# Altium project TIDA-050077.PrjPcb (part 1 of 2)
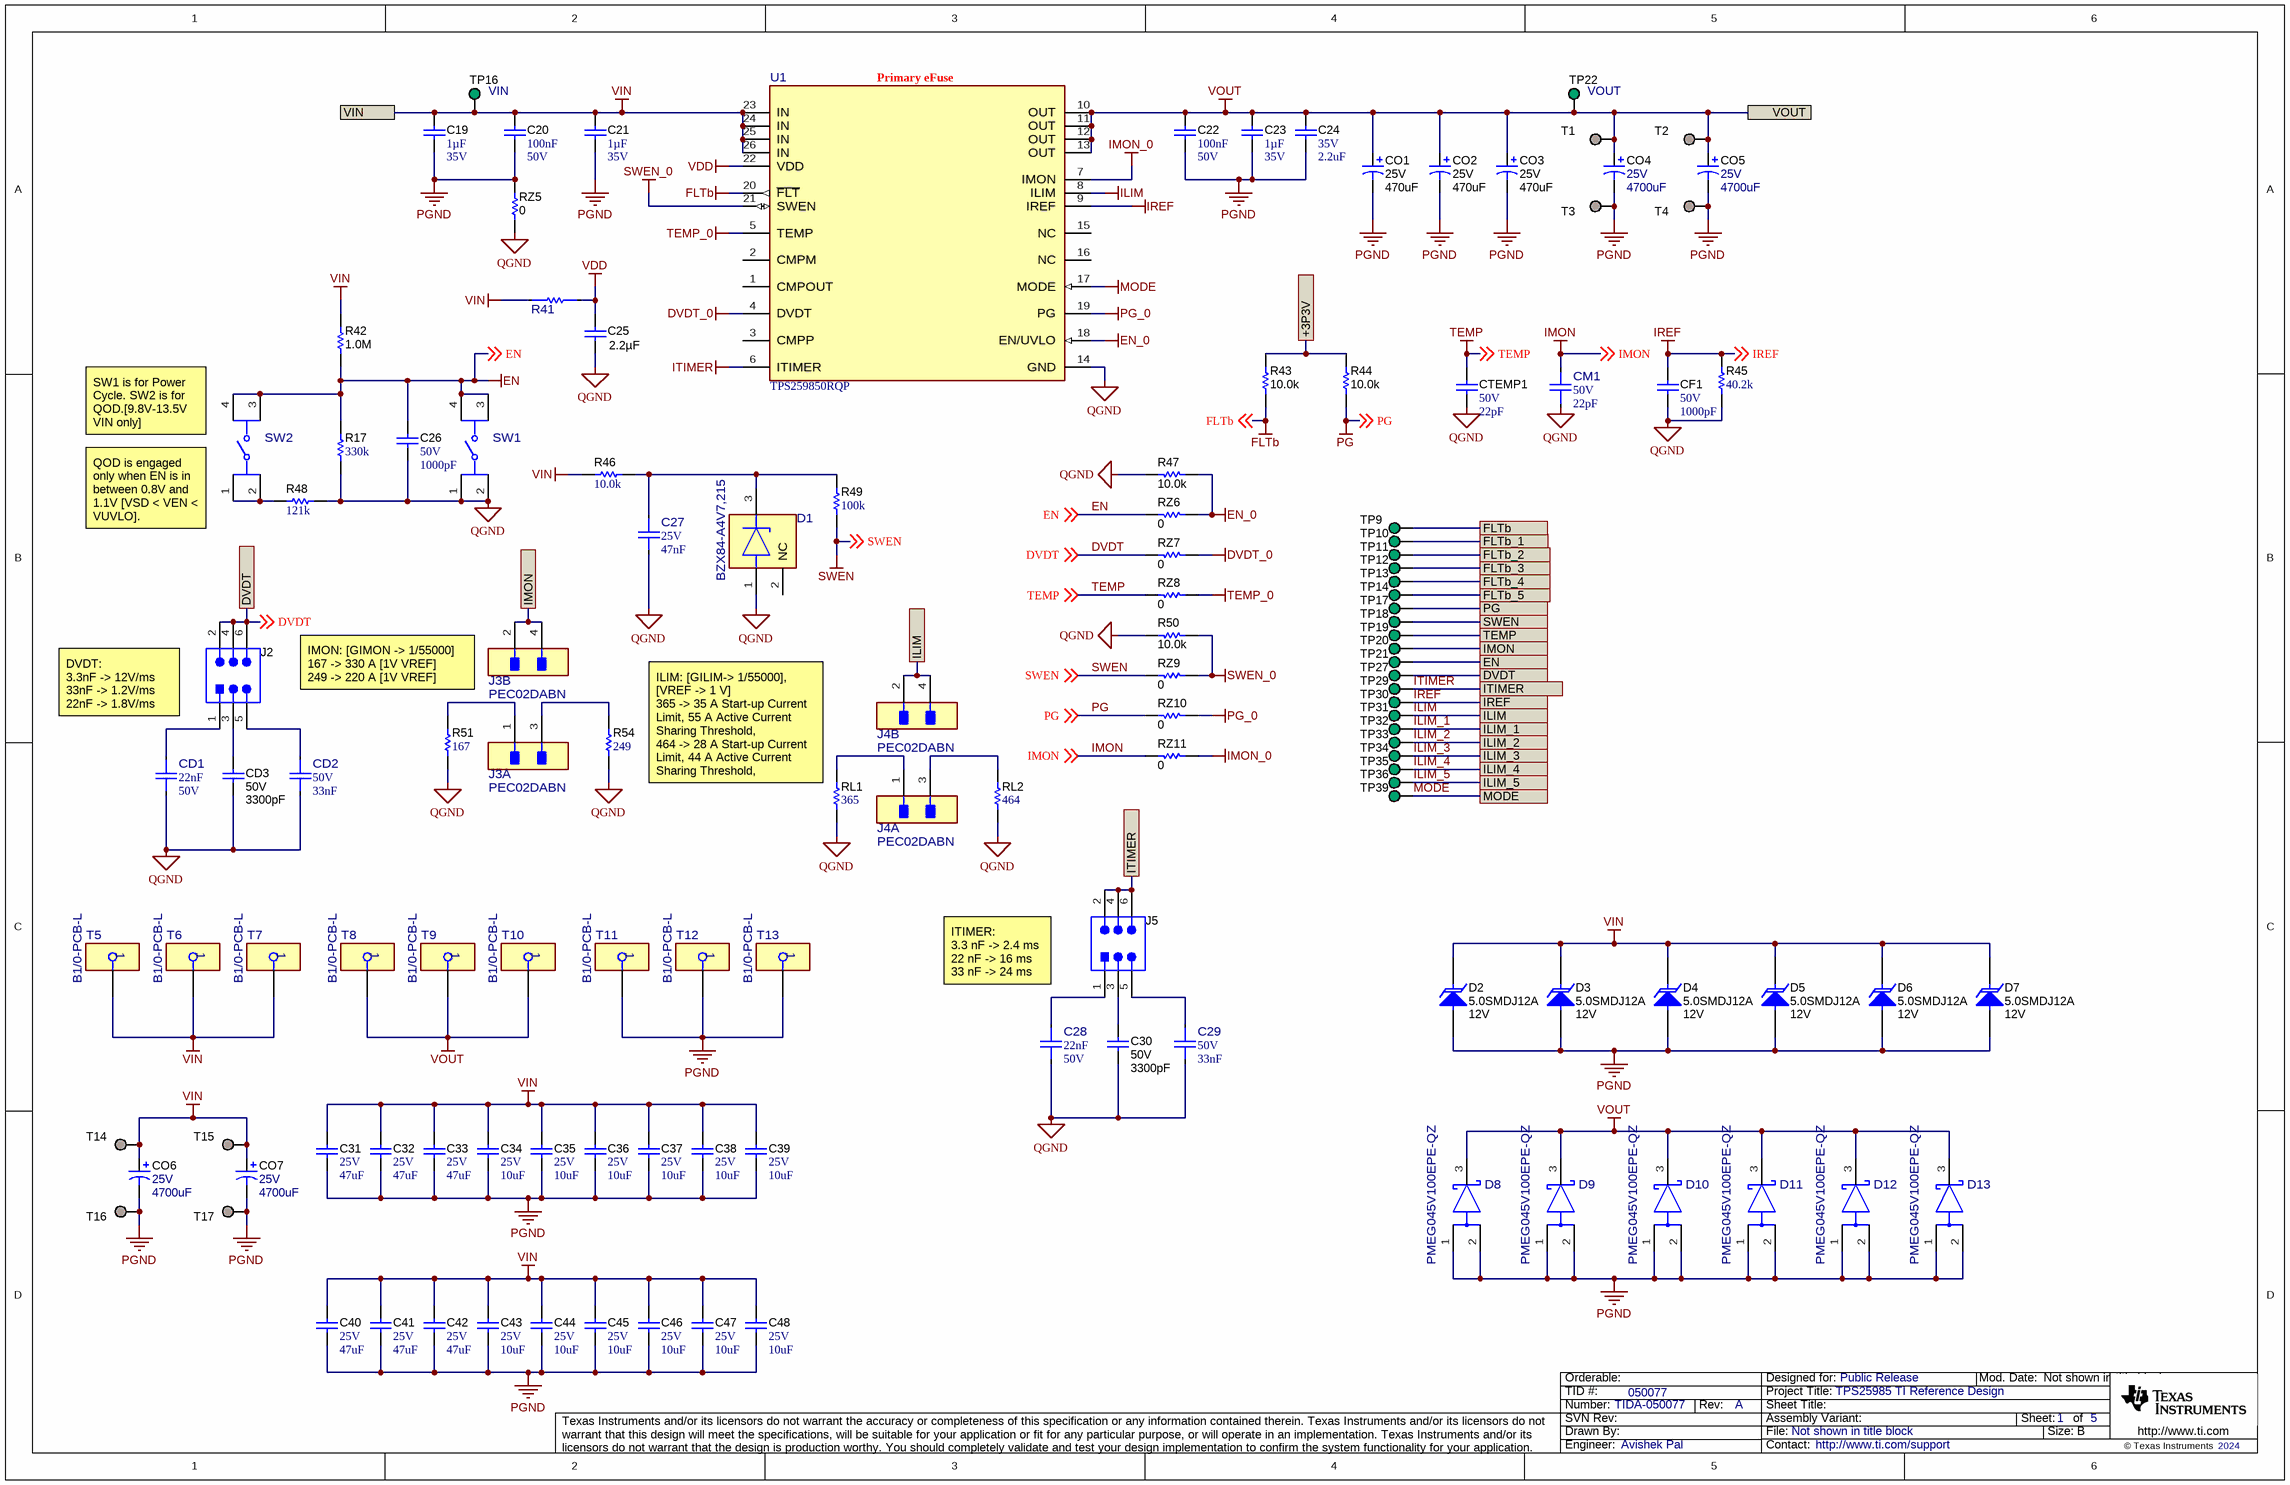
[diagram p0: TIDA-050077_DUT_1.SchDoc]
CopyrightYear: 2024; PCB_Rev: A; PRJ_Customer: Public Release; PRJ_Engineer: Avishek Pal; PRJ_Number: TIDA-050077; PRJ_Title: TPS25985 TI Reference Design; SCH_Rev: A; TechSupport: http://www.ti.com/support; TID: 050077
5 sheets, 376 parts. Net scope: flat (ports and power ports of the same name join across sheets).
Board file: TIDA-050077_PCB-112723-1m.PcbDoc
Sheets:
  TIDA-050077_DUT_1.SchDoc
  TIDA-050077_DUT_2_3_4.SchDoc
  TIDA-050077_DUT_5_6.SchDoc
  TIDA-050077_HKeeping.SchDoc
  TIDA-050077_Hardware.SchDoc

## Sheet TIDA-050077_DUT_1.SchDoc
size 431 x 279 mm; Date: Not shown in title block; ApprovedBy: Not shown in title block; CheckedBy: Not shown in title block; Author: Not shown in title block; CompanyName: Not shown in title block; Engineer: Not shown in title block; Organization: Not shown in title block; Address1: Not shown in title block; Address2: Not shown in title block; Address3: Not shown in title block; Address4: Not shown in title block; DocumentNumber: 1; Revision: Use project parameter SCH_Rev; SheetNumber: 1; SheetTotal: 5; PageSetup: Record=PageOptions¦CenterHorizontal=True¦CenterVertical=True¦PrintScale=1.00¦XCorrection=1.00¦YCorrection=1.00¦PrintKind=0¦BorderSize=5000000¦LeftOffset=0¦BottomOffset=0¦Orientation=2¦PaperLength=1000¦PaperWidth=1000¦Scale=100¦PaperSource=15¦PrintQuality=600¦MediaType=1¦DitherType=10¦PaperKind=Letter¦PrintScaleMode=1

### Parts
C19  Cap_F: 1µF  VDC_V: 35V  [0603]  (hidden comment: C1608X7R1V105K080AC)
C20  Cap_F: 100nF  VDC_V: 50V  [0603]  (hidden comment: C0603C104K5RACAUTO)
C21  Cap_F: 1µF  VDC_V: 35V  [0603]  (hidden comment: C1608X7R1V105K080AC)
C22  Cap_F: 100nF  VDC_V: 50V  [0603]  (hidden comment: C0603C104K5RACAUTO)
C23  Cap_F: 1µF  VDC_V: 35V  [0603]  (hidden comment: C1608X7R1V105K080AC)
C24  VDC_V: 35V  ValueDisplayed: 2.2uF  [0603]  (hidden comment: GRM188R6YA225KA12D)
C25  ValueDisplayed: 2.2µF  [0603L]  (hidden comment: GRM188C71E225KE11D)
C26  VDC_V: 50V  ValueDisplayed: 1000pF  [0603]  (hidden comment: GRM1885C1H102JA01D)
C27  VDC_V: 25V  Cap_F: 47nF  [FP-C0603C473J3RAC7867_0603-MFG]  (hidden comment: C0603C473J3RAC7867)
C28  Cap_F: 22nF  VDC_V: 50V  [FP-GCJ188R71H223KA01D_0603-MFG]  (hidden comment: GCJ188R71H223KA01D)
C29  VDC_V: 50V  Cap_F: 33nF  [FP-GCJ188R71H333KA12D_0603-MFG]  (hidden comment: GCJ188R71H333KA12D)
C30  VDC_V: 50V  ValueDisplayed: 3300pF  [0603]  (hidden comment: GRM1885C1H332JA01D)
C31  VDC_V: 25V  ValueDisplayed: 47uF  [CKG57N]  (hidden comment: CKG57NX7S1E476M500JH)
C32  VDC_V: 25V  ValueDisplayed: 47uF  [CKG57N]  (hidden comment: CKG57NX7S1E476M500JH)
C33  VDC_V: 25V  ValueDisplayed: 47uF  [CKG57N]  (hidden comment: CKG57NX7S1E476M500JH)
C34  VDC_V: 25V  ValueDisplayed: 10uF  [0805_HV]  (hidden comment: C2012X5R1E106K125AB)
C35  VDC_V: 25V  ValueDisplayed: 10uF  [0805_HV]  (hidden comment: C2012X5R1E106K125AB)
C36  VDC_V: 25V  ValueDisplayed: 10uF  [0805_HV]  (hidden comment: C2012X5R1E106K125AB)
C37  VDC_V: 25V  ValueDisplayed: 10uF  [0805_HV]  (hidden comment: C2012X5R1E106K125AB)
C38  VDC_V: 25V  ValueDisplayed: 10uF  [0805_HV]  (hidden comment: C2012X5R1E106K125AB)
C39  VDC_V: 25V  ValueDisplayed: 10uF  [0805_HV]  (hidden comment: C2012X5R1E106K125AB)
C40  VDC_V: 25V  ValueDisplayed: 47uF  [CKG57N]  (hidden comment: CKG57NX7S1E476M500JH)
C41  VDC_V: 25V  ValueDisplayed: 47uF  [CKG57N]  (hidden comment: CKG57NX7S1E476M500JH)
C42  VDC_V: 25V  ValueDisplayed: 47uF  [CKG57N]  (hidden comment: CKG57NX7S1E476M500JH)
C43  VDC_V: 25V  ValueDisplayed: 10uF  [0805_HV]  (hidden comment: C2012X5R1E106K125AB)
C44  VDC_V: 25V  ValueDisplayed: 10uF  [0805_HV]  (hidden comment: C2012X5R1E106K125AB)
C45  VDC_V: 25V  ValueDisplayed: 10uF  [0805_HV]  (hidden comment: C2012X5R1E106K125AB)
C46  VDC_V: 25V  ValueDisplayed: 10uF  [0805_HV]  (hidden comment: C2012X5R1E106K125AB)
C47  VDC_V: 25V  ValueDisplayed: 10uF  [0805_HV]  (hidden comment: C2012X5R1E106K125AB)
C48  VDC_V: 25V  ValueDisplayed: 10uF  [0805_HV]  (hidden comment: C2012X5R1E106K125AB)
CD1  Cap_F: 22nF  VDC_V: 50V  [FP-GCJ188R71H223KA01D_0603-MFG]  (hidden comment: GCJ188R71H223KA01D)
CD2  VDC_V: 50V  Cap_F: 33nF  [FP-GCJ188R71H333KA12D_0603-MFG]  (hidden comment: GCJ188R71H333KA12D)
CD3  VDC_V: 50V  ValueDisplayed: 3300pF  [0603]  (hidden comment: GRM1885C1H332JA01D)
CF1  VDC_V: 50V  ValueDisplayed: 1000pF  [0402]  (hidden comment: CGA2B2C0G1H102J050BA)
CM1  VDC_V: 50V  ValueDisplayed: 22pF  [FP-GCG1885G1H220JA01D_0603-IPC_C]  (hidden comment: GCG1885G1H220JA01D)
CO1  VDC_V: 25V  ValueDisplayed: 470uF  [CAPSMT_62_JA0]  (hidden comment: EMVE250ADA471MJA0G)
CO2  VDC_V: 25V  ValueDisplayed: 470uF  [CAPSMT_62_JA0]  (hidden comment: EMVE250ADA471MJA0G)
CO3  VDC_V: 25V  ValueDisplayed: 470uF  [CAPSMT_62_JA0]  (hidden comment: EMVE250ADA471MJA0G)
CO4  VDC_V: 25V  ValueDisplayed: 4700uF  [KMQ_1600x2500]  (hidden comment: EKMQ250EIV472ML25S)
CO5  VDC_V: 25V  ValueDisplayed: 4700uF  [KMQ_1600x2500]  (hidden comment: EKMQ250EIV472ML25S)
CO6  VDC_V: 25V  ValueDisplayed: 4700uF  [KMQ_1600x2500]  (hidden comment: EKMQ250EIV472ML25S)
CO7  VDC_V: 25V  ValueDisplayed: 4700uF  [KMQ_1600x2500]  (hidden comment: EKMQ250EIV472ML25S)
CTEMP1  VDC_V: 50V  ValueDisplayed: 22pF  [0603]  (hidden comment: 06035A220JAT2A)
D1  BZX84-A4V7,215  [FP-BZX84-A4V7,215_SOT23-3-MFG]
D2  5.0SMDJ12A  value 12V  [SMC]
D3  5.0SMDJ12A  value 12V  [SMC]
D4  5.0SMDJ12A  value 12V  [SMC]
D5  5.0SMDJ12A  value 12V  [SMC]
D6  5.0SMDJ12A  value 12V  [SMC]
D7  5.0SMDJ12A  value 12V  [SMC]
D8  PMEG045V100EPE-QZ  [FP-PMEG045V100EPE-QZ_CFP15B-MFG]
D9  PMEG045V100EPE-QZ  [FP-PMEG045V100EPE-QZ_CFP15B-MFG]
D10  PMEG045V100EPE-QZ  [FP-PMEG045V100EPE-QZ_CFP15B-MFG]
D11  PMEG045V100EPE-QZ  [FP-PMEG045V100EPE-QZ_CFP15B-MFG]
D12  PMEG045V100EPE-QZ  [FP-PMEG045V100EPE-QZ_CFP15B-MFG]
D13  PMEG045V100EPE-QZ  [FP-PMEG045V100EPE-QZ_CFP15B-MFG]
J2  PEC03DAAN  [SULLINS_PEC03DAAN]  (value not drawn)
J3  PEC02DABN  [FP-PEC02DABN_HDR4-MFG]  (parts A,B of 2)
J4  PEC02DABN  [FP-PEC02DABN_HDR4-MFG]  (parts A,B of 2)
J5  PEC03DAAN  [SULLINS_PEC03DAAN]  (value not drawn)
R17  ValueDisplayed: 330k  [0402]  (hidden comment: CRCW0402330KFKED)
R41  RC0603JR-0710RL  [FP-RC0603JR-0710RL_0603-MFG]  (value not drawn)
R42  ValueDisplayed: 1.0M  [0402L]  (hidden comment: CRCW04021M00JNED)
R43  ValueDisplayed: 10.0k  [0402]  (hidden comment: RC0402FR-0710KL)
R44  ValueDisplayed: 10.0k  [0402]  (hidden comment: RC0402FR-0710KL)
R45  ValueDisplayed: 40.2k  [0603]  (hidden comment: RT0603BRD0740K2L)
R46  ValueDisplayed: 10.0k  [0603]  (hidden comment: CRCW060310K0FKEA)
R47  ValueDisplayed: 10.0k  [0402]  (hidden comment: RC0402FR-0710KL)
R48  ValueDisplayed: 121k  [0603]  (hidden comment: RC0603FR-07121KL)
R49  ValueDisplayed: 100k  [0402]  (hidden comment: CRCW0402100KFKED)
R50  ValueDisplayed: 10.0k  [0402]  (hidden comment: RC0402FR-0710KL)
R51  ValueDisplayed: 167  [0603]  (hidden comment: RT0603BRD07167RL)
R54  ValueDisplayed: 249  [0603]  (hidden comment: RT0603BRD07249RL)
RL1  ValueDisplayed: 365  [0603]  (hidden comment: RT0603BRD07365RL)
RL2  ValueDisplayed: 464  [0603]  (hidden comment: RT0603BRD07464RL)
RZ5  ValueDisplayed: 0  [0402]  (hidden comment: CRCW04020000Z0ED)
RZ6  ValueDisplayed: 0  [0402]  (hidden comment: CRCW04020000Z0ED)
RZ7  ValueDisplayed: 0  [0402]  (hidden comment: CRCW04020000Z0ED)
RZ8  ValueDisplayed: 0  [0402]  (hidden comment: CRCW04020000Z0ED)
RZ9  ValueDisplayed: 0  [0402]  (hidden comment: CRCW04020000Z0ED)
RZ10  ValueDisplayed: 0  [0402]  (hidden comment: CRCW04020000Z0ED)
RZ11  ValueDisplayed: 0  [0402]  (hidden comment: CRCW04020000Z0ED)
SW1  PTS830GM140SMTRLFS  [FP-PTS830GM140SMTRLFS_SMT_3MM05_2MM6-MFG]  (value not drawn)
SW2  PTS830GM140SMTRLFS  [FP-PTS830GM140SMTRLFS_SMT_3MM05_2MM6-MFG]  (value not drawn)
T1  Turret  [CONN_ 0300-2-15-01-47-01-10-0]  (value not drawn)
T2  Turret  [CONN_ 0300-2-15-01-47-01-10-0]  (value not drawn)
T3  Turret  [CONN_ 0300-2-15-01-47-01-10-0]  (value not drawn)
T4  Turret  [CONN_ 0300-2-15-01-47-01-10-0]  (value not drawn)
T5  B1/0-PCB-L  [FP-B1-0-PCB-L_WIRE_LUG_150A_1-0AWG-MFG]
T6  B1/0-PCB-L  [FP-B1-0-PCB-L_WIRE_LUG_150A_1-0AWG-MFG]
T7  B1/0-PCB-L  [FP-B1-0-PCB-L_WIRE_LUG_150A_1-0AWG-MFG]
T8  B1/0-PCB-L  [FP-B1-0-PCB-L_WIRE_LUG_150A_1-0AWG-MFG]
T9  B1/0-PCB-L  [FP-B1-0-PCB-L_WIRE_LUG_150A_1-0AWG-MFG]
T10  B1/0-PCB-L  [FP-B1-0-PCB-L_WIRE_LUG_150A_1-0AWG-MFG]
T11  B1/0-PCB-L  [FP-B1-0-PCB-L_WIRE_LUG_150A_1-0AWG-MFG]
T12  B1/0-PCB-L  [FP-B1-0-PCB-L_WIRE_LUG_150A_1-0AWG-MFG]
T13  B1/0-PCB-L  [FP-B1-0-PCB-L_WIRE_LUG_150A_1-0AWG-MFG]
T14  Turret  [CONN_ 0300-2-15-01-47-01-10-0]  (value not drawn)
T15  Turret  [CONN_ 0300-2-15-01-47-01-10-0]  (value not drawn)
T16  Turret  [CONN_ 0300-2-15-01-47-01-10-0]  (value not drawn)
T17  Turret  [CONN_ 0300-2-15-01-47-01-10-0]  (value not drawn)
TP9  (no value)  [Keystone5126]
TP10  (no value)  [Keystone5126]
TP11  (no value)  [Keystone5126]
TP12  (no value)  [Keystone5126]
TP13  (no value)  [Keystone5126]
TP14  (no value)  [Keystone5126]
TP16  VIN  [Keystone5126]
TP17  (no value)  [Keystone5126]
TP18  (no value)  [Keystone5126]
TP19  (no value)  [Keystone5126]
TP20  (no value)  [Keystone5126]
TP21  (no value)  [Keystone5126]
TP22  VOUT  [Keystone5126]
TP27  (no value)  [Keystone5126]
TP29  (no value)  [Keystone5126]
TP30  (no value)  [Keystone5126]
TP31  (no value)  [Keystone5126]
TP32  (no value)  [Keystone5126]
TP33  (no value)  [Keystone5126]
TP34  (no value)  [Keystone5126]
TP35  (no value)  [Keystone5126]
TP36  (no value)  [Keystone5126]
TP39  (no value)  [Keystone5126]
U1  TPS259850RQP  [RQP0026A-MFG]

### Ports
+3P3V, DVDT, EN, FLTb, FLTb_1, FLTb_2, FLTb_3, FLTb_4, FLTb_5, ILIM, ILIM_1, ILIM_2, ILIM_3, ILIM_4, ILIM_5, IMON, IREF, ITIMER, MODE, PG, SWEN, TEMP, VIN, VOUT

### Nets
+3P3V: R43.1 R44.1 ; port +3P3V
DVDT_0: RZ7.1 U1.4(DVDT)
EN: C26.1 R17.2 R42.1 RZ6.2 SW1.3 SW1.4 SW2.3 SW2.4 ; off-sheet EN
EN_0: R47.2 RZ6.1 U1.18(EN/UVLO)
FLTb: R43.2 U1.20(~{FLT}) ; off-sheet FLTb
ILIM: J4.2 J4.4 TP31.1 U1.8(ILIM) ; port ILIM
IMON: CM1.2 RZ11.2 ; off-sheet IMON
IMON_0: RZ11.1 U1.7(IMON)
IREF: CF1.1 R45.2 TP30.1 U1.9(IREF) ; off-sheet IREF, port IREF
ITIMER: J5.2 J5.4 J5.6 TP29.1 U1.6(ITIMER) ; port ITIMER
MODE: TP39.1 U1.17(MODE) ; port MODE
PG: R44.2 RZ10.2 ; off-sheet PG
PG_0: RZ10.1 U1.19(PG)
PGND: C19.2 C20.2 C21.2 C22.2 C23.2 C24.2 C31.2 C32.2 C33.2 C34.2 C35.2 C36.2 C37.2 C38.2 C39.2 C40.2 C41.2 C42.2 C43.2 C44.2 C45.2 C46.2 C47.2 C48.2 CO1.2(-) CO2.2(-) CO3.2(-) CO4.2(-) CO5.2(-) CO6.2(-) CO7.2(-) D2.2(A) D3.2(A) D4.2(A) D5.2(A) D6.2(A) D7.2(A) D8.1(A) D8.2(A) D9.1(A) D9.2(A) D10.1(A) D10.2(A) D11.1(A) D11.2(A) D12.1(A) D12.2(A) D13.1(A) D13.2(A) RZ5.2 T3.1 T4.1 T11.1 T12.1 T13.1 T16.1 T17.1
QGND: C25.2 C26.2 C27.2 C28.2 C29.2 C30.2 CD1.2 CD2.2 CD3.2 CF1.2 CM1.1 CTEMP1.2 D1.1(A) R17.1 R45.1 R47.1 R48.2 R50.1 R51.1 R54.1 RL1.1 RL2.1 RZ5.1 SW1.1 SW1.2 U1.14(GND)
SWEN: R49.1 RZ9.2 ; off-sheet SWEN
SWEN_0: R50.2 RZ9.1 U1.21(SWEN)
TEMP: CTEMP1.1 RZ8.2 ; off-sheet TEMP
TEMP_0: RZ8.1 U1.5(TEMP)
VDD: C25.1 R41.2 U1.22(VDD)
VIN: C19.1 C20.1 C21.1 C31.1 C32.1 C33.1 C34.1 C35.1 C36.1 C37.1 C38.1 C39.1 C40.1 C41.1 C42.1 C43.1 C44.1 C45.1 C46.1 C47.1 C48.1 CO6.1(+) CO7.1(+) D2.1(K) D3.1(K) D4.1(K) D5.1(K) D6.1(K) D7.1(K) R41.1 R42.2 R46.1 T5.1 T6.1 T7.1 T14.1 T15.1 TP16.1 U1.23(IN) U1.24(IN) U1.25(IN) U1.26(IN) ; port VIN
VOUT: C22.1 C23.1 C24.1 CO1.1(+) CO2.1(+) CO3.1(+) CO4.1(+) CO5.1(+) D8.3(K) D9.3(K) D10.3(K) D11.3(K) D12.3(K) D13.3(K) T1.1 T2.1 T8.1 T9.1 T10.1 TP22.1 U1.10(OUT) U1.11(OUT) U1.12(OUT) U1.13(OUT) ; port VOUT
DVDT: J2.2 J2.4 J2.6 RZ7.2 TP27.1 ; off-sheet DVDT, port DVDT
ILIM_1: TP32.1 ; port ILIM_1
ILIM_2: TP33.1 ; port ILIM_2
ILIM_3: TP34.1 ; port ILIM_3
ILIM_4: TP35.1 ; port ILIM_4
ILIM_5: TP36.1 ; port ILIM_5
NetC27_1: C27.1 D1.3(K) R46.2 R49.2
NetC28_1: C28.1 J5.1
NetC29_1: C29.1 J5.5
NetC30_1: C30.1 J5.3
NetCD1_1: CD1.1 J2.1
NetCD2_1: CD2.1 J2.5
NetCD3_1: CD3.1 J2.3
NetJ3_1: J3.1 R51.2
NetJ3_2: J3.2 J3.4 TP20.1 ; port IMON
NetJ3_3: J3.3 R54.2
NetJ4_1: J4.1 RL1.2
NetJ4_3: J4.3 RL2.2
NetQ1_1: TP17.1 ; port PG
NetQ2_1: TP9.1 ; port FLTb
NetQ3_1: TP10.1 ; port FLTb_1
NetQ4_1: TP11.1 ; port FLTb_2
NetQ5_1: TP12.1 ; port FLTb_3
NetQ6_1: TP13.1 ; port FLTb_4
NetQ7_1: TP14.1 ; port FLTb_5
NetR48_1: R48.1 SW2.1 SW2.2
NetTP18_1: TP18.1 ; port SWEN
NetTP19_1: TP19.1 ; port TEMP
NetTP21_1: TP21.1 ; port EN

Not connected (* = marked no-connect by the designer): D1 2(NC); U1 1(CMPOUT) 2(CMPM) 3(CMPP) 15(NC) 16(NC)

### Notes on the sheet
- (near U1) Primary eFuse
- (near SW2) SW1 is for Power Cycle. SW2 is for QOD.[9.8V-13.5V VIN only]
- (near SW2) QOD is engaged only when EN is in between 0.8V and 1.1V [VSD < VEN < VUVLO].
- IMON: [GIMON -> 1/55000]
  167 -> 330 A [1V VREF]
  249 -> 220 A [1V VREF]
- DVDT:
  3.3nF -> 12V/ms
  33nF -> 1.2V/ms
  22nF -> 1.8V/ms
- (near RL1) ILIM: [GILIM-> 1/55000], [VREF -> 1 V]
  365 -> 35 A Start-up Current Limit, 55 A Active Current Sharing Threshold,
  464 -> 28 A Start-up Current Limit, 44 A Active Current Sharing Threshold,
- ITIMER:
  3.3 nF -> 2.4 ms
  22 nF -> 16 ms
  33 nF -> 24 ms

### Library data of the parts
C19 C21 C23 = CMP-0007052-1: CAP, CERM, 1 uF, 35 V, +/- 10%, X7R, 0603; Manufacturer: TDK; TaMin_C: -55°C; Polarized: N; SizeAreaWB_mm2: 4.68; Value1: Unknown; U/M: EA; Value: 1uF; TaMax_C: 125°C; SizeZ_mm: 1; SizeX_mm: 1.6; SizeY_mm: 0.8; SizeArea_mm2: 1.28; AEC Category: Q200
C20 C22 = CMP-0079602-1: CAP, CERM, 0.1 µF, 50 V,+/- 10%, X7R, AEC-Q200 Grade 1, 0603; Manufacturer: Kemet; TaMin_C: -55°C; Polarized: N; SizeAreaWB_mm2: 4.68; U/M: EA; Value: 0.1uF; TaMax_C: 125°C; SizeZ_mm: 1; SizeX_mm: 1.6; SizeY_mm: 0.8; SizeArea_mm2: 1.28; AEC Qualified: Y; AEC Category: Q200; ValueDisplayed: 0.1µF
C24 = CMP-0007356-5: CAP, CERM, 2.2 uF, 35 V, +/- 10%, X5R, 0603; Manufacturer: MuRata; TaMin_C: -55°C; Polarized: N; SizeAreaWB_mm2: 4.68; Value1: Unknown; U/M: EA; Value: 2.2uF; TaMax_C: 85°C; SizeZ_mm: 1; SizeX_mm: 1.6; SizeY_mm: 0.8; SizeArea_mm2: 1.28; Cap_F: 2.2µF; AEC Category: Q200
C25 = CMP-0075366-1: CAP, CERM, 2.2 µF, 25 V,+/- 10%, X7S, 0603; Manufacturer: MuRata; TaMin_C: -55°C; Polarized: N; SizeAreaWB_mm2: 4.68; U/M: EA; Value: 2.2uF; TaMax_C: 125°C; SizeZ_mm: 1.0; SizeX_mm: 1.6; SizeY_mm: 0.8; Cap_Case: 0603; Value2: 25V; SizeArea_mm2: 1.28; AEC Category: Q200
C26 = CMP-0007173-1: CAP, CERM, 1000 pF, 50 V, +/- 5%, C0G/NP0, 0603; Manufacturer: MuRata; TaMin_C: -55°C; Polarized: N; SizeAreaWB_mm2: 4.68; Value1: Unknown; U/M: EA; Value: 1000pF; TaMax_C: 125°C; SizeZ_mm: 1; SizeX_mm: 1.6; SizeY_mm: 0.8; SizeArea_mm2: 1.28; Cap_F: 1nF; AEC Category: Q200
C27 = CMP-0095698-1: Cap Ceramic 0.047uF 25V X7R 5% SMD 0603 125°C Paper T/R; Manufacturer: KEMET; AEC Qualified: No; SizeZ_mm: 0.87mm; TempCo: 15%; Value: 47nF
C28 CD1 = CMP-0095694-1: Cap Ceramic 22000pF 50V X7R 10% Pad SMD 0603 Soft Termination +125°C Automotive T/R; Manufacturer: Murata; AEC Qualified: Yes; AEC Grade: Grade 1; TempCo: 15%; SizeZ_mm: 0.9mm; Value: 22nF
C29 CD2 = CMP-0095695-1: Cap Ceramic 33000pF 50V X7R 10% Pad SMD 0603 Soft Termination +125°C Automotive T/R; Manufacturer: Murata; TempCo: 15%; AEC Grade: Grade 1; AEC Qualified: Yes; SizeZ_mm: 0.9mm; Value: 33nF
C30 CD3 = CMP-0007210-3: CAP, CERM, 3300 pF, 50 V, +/- 5%, C0G/NP0, 0603; Manufacturer: MuRata; TaMin_C: -55°C; Polarized: N; SizeAreaWB_mm2: 4.68; Value1: Unknown; U/M: EA; Value: 3300pF; TaMax_C: 125°C; SizeZ_mm: 1; SizeX_mm: 1.6; SizeY_mm: 0.8; SizeArea_mm2: 1.28; Cap_F: 3.3nF; AEC Category: Q200
C31-C33 C40-C42 = CMP-0009426-2: CAP, CERM, 47 uF, 25 V, +/- 20%, X7S, 6x5x5mm; Manufacturer: TDK; TaMin_C: -55°C; Polarized: N; SizeAreaWB_mm2: 56; Value1: Unknown; U/M: EA; Value: 47uF; TaMax_C: 125°C; SizeZ_mm: 5.5; SizeX_mm: 6; SizeY_mm: 5; Cap_Case: 2220; SizeArea_mm2: 30; Cap_F: 47µF; AEC Category: Q200
C34-C39 C43-C48 = CMP-0007828-2: CAP, CERM, 10 uF, 25 V, +/- 10%, X5R, 0805; Manufacturer: TDK; TaMin_C: -55°C; Polarized: N; SizeAreaWB_mm2: 6.75; Value1: Unknown; U/M: EA; Value: 10uF; TaMax_C: 85°C; SizeZ_mm: 1.45; SizeX_mm: 2; SizeY_mm: 1.25; Cap_Case: 0805; SizeArea_mm2: 2.5; Cap_F: 10µF; AEC Category: Q200
CF1 = CMP-0006309-1: CAP, CERM, 1000 pF, 50 V, +/- 5%, C0G/NP0, AEC-Q200 Grade 1, 0402; Manufacturer: TDK; TaMin_C: -55°C; Polarized: N; SizeAreaWB_mm2: 3; Value1: Unknown; U/M: EA; Value: 1000pF; TaMax_C: 125°C; SizeZ_mm: 0.6; SizeX_mm: 1; SizeY_mm: 0.5; AEC Qualified: Y; Cap_F: 1nF; AEC Category: Q200
CM1 = CMP-0095693-1: AgPd Termination Conductive Glue Mounting Chip Multilayer Ceramic Capacitors for Automotive 22pF with 5% as tolerance, 50V X8G 30ppm/°C, 0603 Package; Manufacturer: Murata; Tolerance_%: 0.05%; AEC Qualified: Yes; SizeZ_mm: 0.9mm; AEC Grade: Grade 0
CO1-CO3 = CMP-0010865-1: CAP, AL, 470 uF, 25 V, +/- 20%, SMD; Manufacturer: Chemi-Con; TaMin_C: -40°C; Polarized: Y; SizeAreaWB_mm2: 151.29; Value1: Unknown; U/M: EA; Value: 470uF; TaMax_C: 105°C; SizeZ_mm: 10; SizeX_mm: 10.3; Cap_Case: JA0; SizeArea_mm2: 106.09; CompType: Capacitor; Cap_F: 470µF; IRMS_A: 490mA; AEC Category: Q200
CO4-CO7 = CMP-0010371-1: CAP, AL, 4700 uF, 25 V, +/- 20%, TH; Manufacturer: Chemi-Con; TaMin_C: -55°C; Polarized: Y; SizeAreaWB_mm2: 324; Value1: Unknown; U/M: EA; Value: 4700uF; TaMax_C: 105°C; SizeZ_mm: 26.5; SizeX_mm: 16; Cap_Case: 16x25mm; SizeArea_mm2: 256; CompType: Capacitor; AEC Qualified: N; Cap_F: 4.7mF; IRMS_A: 1.57A; AEC Category: Q200
CTEMP1 = CMP-0006775-4: CAP, CERM, 22 pF, 50 V, +/- 5%, C0G/NP0, 0603; Manufacturer: AVX; TaMin_C: -55°C; ESR_ohm: 0.259; Polarized: N; SizeAreaWB_mm2: 4.68; Value1: 0.259 ohm; U/M: EA; Value: 22pF; TaMax_C: 125°C; SizeZ_mm: 1; SizeX_mm: 1.6; SizeY_mm: 0.8; SizeArea_mm2: 1.28; AEC Category: Q200
D1 = CMP-0095562-1: Zener Diode 4.7 V 250 mW ±1% Surface Mount TO-236AB; Manufacturer: Nexperia; AEC Grade: Grade 0; Zener Impedance: 50Ω; TaMax_C: +150°C; TJmax_C: 150°C; AEC Qualified: Yes; Vf_V: 4.75V; Max Reverse Leakage Current: 3uA; Vr_V: 2V; Forward Current: 200mA; Power_W: 250mW; Standoff Height: 0.1mm; SizeZ_mm: 1.1mm
D2-D7 = CMP-0005677-4: Diode, TVS, Uni, 12 V, 19.9 Vc, SMC; Manufacturer: Littelfuse; RJA_CperW: 75; Ipp: 252A; Ppk: 5kW; SizeAreaWB_mm2: 83.2686; Vc: 19.9V; SizeZ_mm: 2.6; SizeY_mm: 6.22; Value1: 5000W; SizeArea_mm2: 50.5686; AEC Category: Q101; Vbr_Max: 14.7V; Vbr_Min: 13.3V; SizeX_mm: 8.13
D8-D13 = CMP-0098305-1: Diode Schottky 45V 10A Surface Mount CFP15B; Manufacturer: Nexperia; AEC Qualified: Yes; SizeZ_mm: 0.99mm; TJmax_C: 175°C; AEC Grade: Grade 0; Cap_F: 1140pF; Forward Current: 14A; Max Surge Forward Current: 300A; Peak Reverse Current: 150uA; TaMax_C: +175°C; TaMin_C: -55°C
J2 J5 = CMP-0054552-1: Header, 100mil, 3x2, Tin, TH; Manufacturer: Sullins Connector Solutions; CNHeader: TRUE; Current_A: 3A; Green_Lifecycle: Not Set; Shrouded: N; Gender: Male; Green_REACh: Incomplete; Voltage_V: 1.8kV; Row_Count: 2; RowSpacing_mm: 2.54; CT: FALSE; Cert_UL: Y
J3 J4 = CMP-0095565-1: Manufacturer: Sullins Connector Solutions; AEC Qualified: No; Current_A: 3A; ContactFinish: Tin,Nickel; Conn Gender: Male; Conn Orientation: Straight; DUT-Pitch_mm: 2.54mm; SizeZ_mm: 8.71mm; Row_Count: 2
R17 = CMP-0078210-2: RES, 330 k, 1%, 0.063 W, AEC-Q200 Grade 0, 0402; Manufacturer: Vishay-Dale; SizeArea_mm2: 0.5; AEC Qualified: Y; AEC Category: Q200; Value: 330k; SizeZ_mm: 0.6; TempCo: 100 ppm/C; AEC Grade: 0; Power_W: 63mW; VDC_V: 50V; Value2: 0.063W; SizeX_mm: 1
R41 = CMP-0095691-1: Res General Purpose Thick Film 0603 10 Ohm 5% 1/10W ±200ppm/°C Molded SMD Paper T/R; Manufacturer: Yageo; Res_ohm: 10; AEC Qualified: No; Value: 10; SizeZ_mm: 0.55mm; Power_W: 100mW; VDC_V: 75V
R42 = CMP-0026859-1: RES, 1.0 M, 5%, 0.063 W, 0402; Manufacturer: Vishay-Dale; Power_W: 63mW; TempCo: 200 ppm/C; Value_Code: 1M00; U/M: EA; Value: 1.0Meg; EIA_Code: E24; Res_ohm: 1M; SizeX_mm: 1; SizeY_mm: 0.5; SizeZ_mm: 0.6; Value2: 0.063W; VDC_V: 50V; AEC Category: Q200
R43 R44 R47 R50 = CMP-0078669-1: RES, 10.0 k, 1%, 0.063 W, 0402; Manufacturer: Yageo America; Power_W: 63mW; Green_Lifecycle: Active; TempCo: 100 ppm/C; Value_Code: 10k0; Green_REACh: Passed; Value: 10.0k; EIA_Code: E96; Res_ohm: 10k; SizeX_mm: 1; SizeY_mm: 0.5; SizeZ_mm: 0.6; Value2: 0.063W; AEC Qualified: N; AEC Category: Q200
R45 = CMP-0024214-3: RES, 40.2 k, 0.1%, 0.1 W, 0603; Manufacturer: Yageo America; Power_W: 100mW; TempCo: 25 ppm/C; Value_Code: 40k2; U/M: EA; Value: 40.2k; EIA_Code: E192; SizeX_mm: 1.6; SizeY_mm: 0.8; SizeZ_mm: 1; Value2: 0.1W; SizeArea_mm2: 1.28; VDC_V: 75V; AEC Category: Q200
R46 = CMP-0021998-4: RES, 10.0 k, 1%, 0.1 W, AEC-Q200 Grade 0, 0603; Manufacturer: Vishay-Dale; Power_W: 100mW; TempCo: 100 ppm/C; Value_Code: 10k0; Value: 10.0k; EIA_Code: E96; Res_ohm: 10k; SizeX_mm: 1.6; SizeY_mm: 0.8; SizeZ_mm: 1; Value2: 0.1W; SizeArea_mm2: 1.28; AEC Qualified: Y; VDC_V: 75V; AEC Category: Q200; AEC Grade: 0
R48 = CMP-0022770-4: RES, 121 k, 1%, 0.1 W, 0603; Manufacturer: Yageo; Power_W: 100mW; TempCo: 100 ppm/C; Value: 121k; EIA_Code: E96; SizeX_mm: 1.6; SizeY_mm: 0.8; SizeZ_mm: 1; Value2: 0.1W; SizeArea_mm2: 1.28; AEC Qualified: N; VDC_V: 75V; AEC Category: Q200; SizeAreaWB_mm2: 4.68
R49 = CMP-0025950-1: RES, 100 k, 1%, 0.063 W, 0402; Manufacturer: Vishay-Dale; Power_W: 63mW; TempCo: 100 ppm/C; U/M: EA; Value: 100k; EIA_Code: E96; SizeX_mm: 1; SizeY_mm: 0.5; SizeZ_mm: 0.6; Value2: 0.063W; VDC_V: 50V; AEC Category: Q200
R51 = CMP-0023795-3: RES, 167, 0.1%, 0.1 W, 0603; Manufacturer: Yageo America; Power_W: 100mW; TempCo: 25 ppm/C; Value_Code: 167R; U/M: EA; Value: 167; EIA_Code: E192; SizeX_mm: 1.6; SizeY_mm: 0.8; SizeZ_mm: 1; Value2: 0.1W; SizeArea_mm2: 1.28; VDC_V: 75V; AEC Category: Q200
R54 = CMP-0023987-2: RES, 249, 0.1%, 0.1 W, 0603; Manufacturer: Yageo America; Power_W: 100mW; TempCo: 25 ppm/C; Value_Code: 249R; U/M: EA; Value: 249; EIA_Code: E192; SizeX_mm: 1.6; SizeY_mm: 0.8; SizeZ_mm: 1; Value2: 0.1W; SizeArea_mm2: 1.28; VDC_V: 75V; AEC Category: Q200
RL1 = CMP-0024153-1: RES, 365, 0.1%, 0.1 W, 0603; Manufacturer: Yageo America; Power_W: 100mW; TempCo: 25 ppm/C; Value_Code: 365R; U/M: EA; Value: 365; EIA_Code: E192; SizeX_mm: 1.6; SizeY_mm: 0.8; SizeZ_mm: 1; Value2: 0.1W; SizeArea_mm2: 1.28; VDC_V: 75V; AEC Category: Q200
RL2 = CMP-0024259-2: RES, 464, 0.1%, 0.1 W, 0603; Manufacturer: Yageo America; Power_W: 100mW; TempCo: 25 ppm/C; Value_Code: 464R; U/M: EA; Value: 464; EIA_Code: E192; SizeX_mm: 1.6; SizeY_mm: 0.8; SizeZ_mm: 1; Value2: 0.1W; SizeArea_mm2: 1.28; VDC_V: 75V; AEC Category: Q200
RZ5-RZ11 = CMP-0026822-3: RES, 0, 5%, 0.063 W, AEC-Q200 Grade 0, 0402; Manufacturer: Vishay-Dale; Power_W: 63mW; TempCo: 200 ppm/C; Value_Code: 0000; Value: 0; EIA_Code: E24; SizeX_mm: 1; SizeY_mm: 0.5; SizeZ_mm: 0.6; Value2: 0.063W; AEC Qualified: Y; VDC_V: 50V; AEC Category: Q200
SW1 SW2 = CMP-0087766-1: Tactile Switch SPST-NO Top Actuated Surface Mount; Manufacturer: C&K Components; VDC_V: 12V; Circuit: SPST; SizeZ_mm: 1.5mm
T1-T4 T14-T17 = CMP-0055005-1: Connector, Receptacle, Pin, TH; Manufacturer: Mill-Max; PartNumber: 0300-2-15-01-47-01-10-0; CompType: PCB Pin; CNHeader: FALSE
T5-T13 = CMP-0093713-2: 1/0 AWG High AMP PCB Wire Lugs 1/0-8 AWG; Manufacturer: INTERNATIONAL HYDRAULICS; Current_A: 150A; ContactFinish: Tin; Is Female: yes; Conn Orientation: Horizontal; AEC Qualified: No; Min Wire Gauge: 1; Conn Gender: Female; Max Wire Gauge: 0
TP9-TP14 TP16-TP22 TP27 TP29-TP36 TP39 = CMP-0055158-1: Test Point, Multipurpose, Green, TH; Manufacturer: Keystone; CNHeader: FALSE; Green_Lifecycle: Active; Green_REACh: Passed; ContactFinish: Silver; CT: TRUE
U1 = CMP-0091052-1: Manufacturer: Texas Instruments; Standoff Height: 0mm; SizeZ_mm: 1mm

## Sheet TIDA-050077_DUT_2_3_4.SchDoc
size 431 x 279 mm; Date: Not shown in title block; ApprovedBy: Not shown in title block; CheckedBy: Not shown in title block; Author: Not shown in title block; CompanyName: Not shown in title block; Engineer: Not shown in title block; Organization: Not shown in title block; Address1: Not shown in title block; Address2: Not shown in title block; Address3: Not shown in title block; Address4: Not shown in title block; DocumentNumber: 2; Revision: Use project parameter SCH_Rev; SheetNumber: 2; SheetTotal: 5; PageSetup: Record=PageOptions¦CenterHorizontal=True¦CenterVertical=True¦PrintScale=1.00¦XCorrection=1.00¦YCorrection=1.00¦PrintKind=0¦BorderSize=5000000¦LeftOffset=0¦BottomOffset=0¦Orientation=2¦PaperLength=1000¦PaperWidth=1000¦Scale=100¦PaperSource=15¦PrintQuality=600¦MediaType=1¦DitherType=10¦PaperKind=Letter¦PrintScaleMode=1
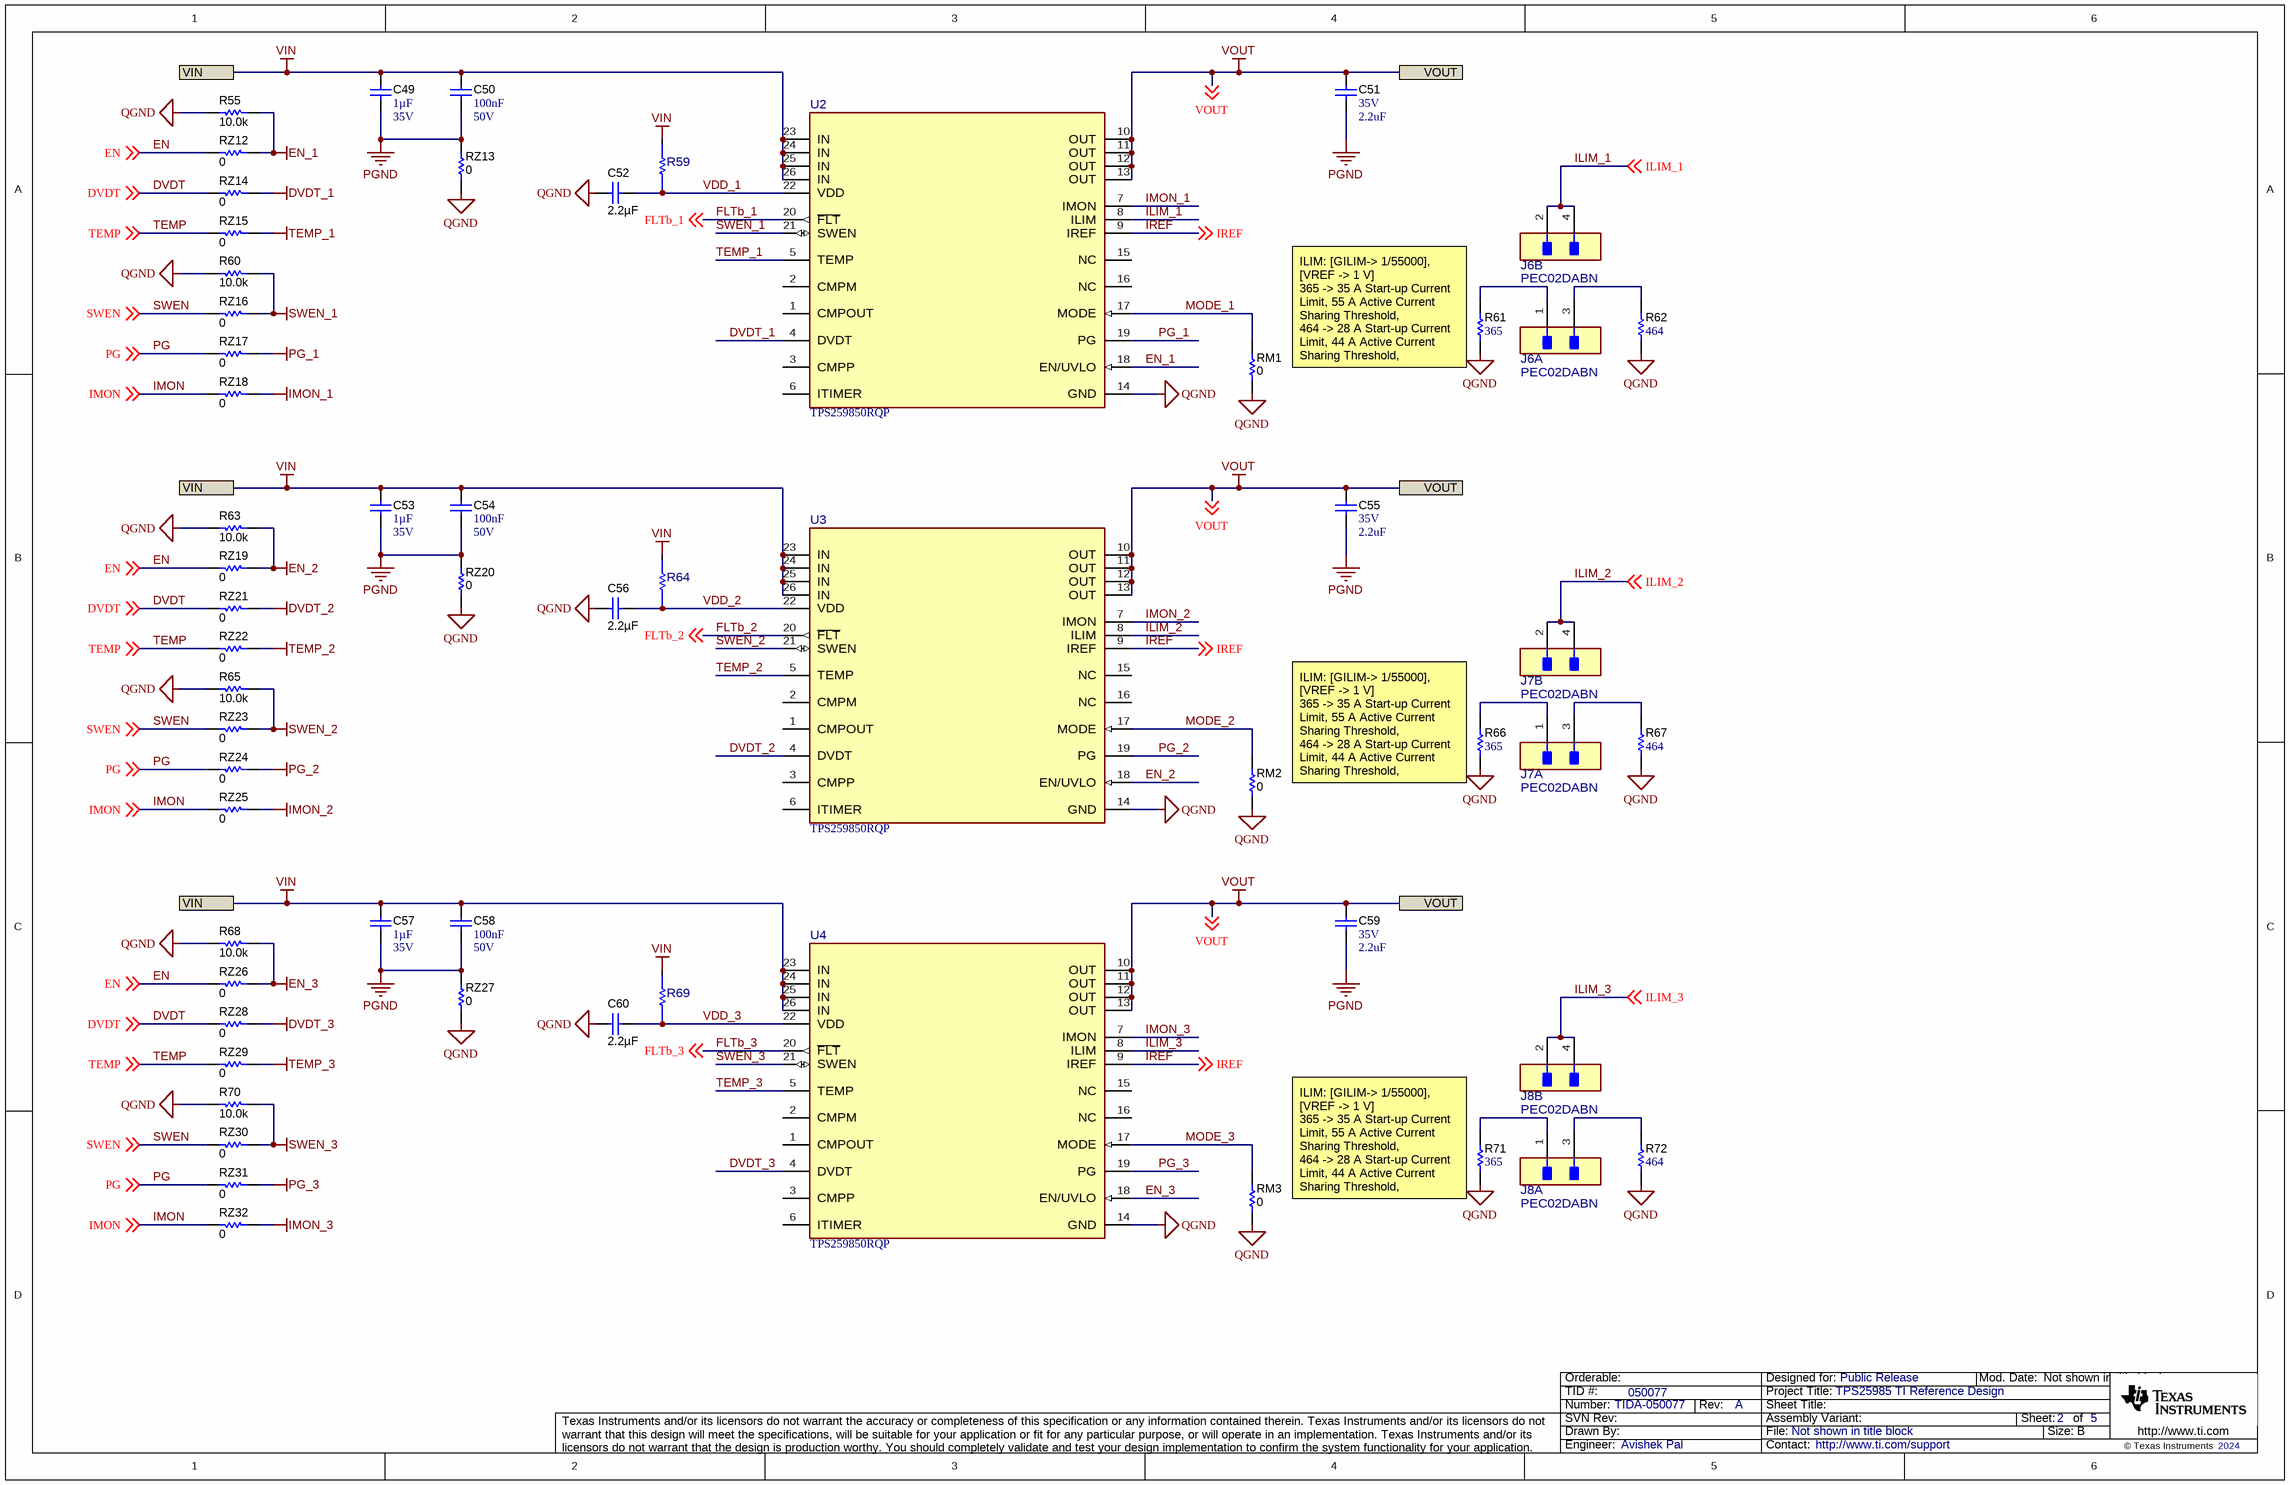
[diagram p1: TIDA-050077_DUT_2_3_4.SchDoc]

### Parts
C49  Cap_F: 1µF  VDC_V: 35V  [0603]  (hidden comment: C1608X7R1V105K080AC)
C50  Cap_F: 100nF  VDC_V: 50V  [0603]  (hidden comment: C0603C104K5RACAUTO)
C51  VDC_V: 35V  ValueDisplayed: 2.2uF  [0603]  (hidden comment: GRM188R6YA225KA12D)
C52  ValueDisplayed: 2.2µF  [0603]  (hidden comment: GRM188C71E225KE11D)
C53  Cap_F: 1µF  VDC_V: 35V  [0603]  (hidden comment: C1608X7R1V105K080AC)
C54  Cap_F: 100nF  VDC_V: 50V  [0603]  (hidden comment: C0603C104K5RACAUTO)
C55  VDC_V: 35V  ValueDisplayed: 2.2uF  [0603]  (hidden comment: GRM188R6YA225KA12D)
C56  ValueDisplayed: 2.2µF  [0603]  (hidden comment: GRM188C71E225KE11D)
C57  Cap_F: 1µF  VDC_V: 35V  [0603]  (hidden comment: C1608X7R1V105K080AC)
C58  Cap_F: 100nF  VDC_V: 50V  [0603]  (hidden comment: C0603C104K5RACAUTO)
C59  VDC_V: 35V  ValueDisplayed: 2.2uF  [0603]  (hidden comment: GRM188R6YA225KA12D)
C60  ValueDisplayed: 2.2µF  [0603]  (hidden comment: GRM188C71E225KE11D)
J6  PEC02DABN  [FP-PEC02DABN_HDR4-MFG]  (parts A,B of 2)
J7  PEC02DABN  [FP-PEC02DABN_HDR4-MFG]  (parts A,B of 2)
J8  PEC02DABN  [FP-PEC02DABN_HDR4-MFG]  (parts A,B of 2)
R55  ValueDisplayed: 10.0k  [0402]  (hidden comment: RC0402FR-0710KL)
R59  RC0603JR-0710RL  [FP-RC0603JR-0710RL_0603-MFG]  (value not drawn)
R60  ValueDisplayed: 10.0k  [0402]  (hidden comment: RC0402FR-0710KL)
R61  ValueDisplayed: 365  [0603]  (hidden comment: RT0603BRD07365RL)
R62  ValueDisplayed: 464  [0603]  (hidden comment: RT0603BRD07464RL)
R63  ValueDisplayed: 10.0k  [0402]  (hidden comment: RC0402FR-0710KL)
R64  RC0603JR-0710RL  [FP-RC0603JR-0710RL_0603-MFG]  (value not drawn)
R65  ValueDisplayed: 10.0k  [0402]  (hidden comment: RC0402FR-0710KL)
R66  ValueDisplayed: 365  [0603]  (hidden comment: RT0603BRD07365RL)
R67  ValueDisplayed: 464  [0603]  (hidden comment: RT0603BRD07464RL)
R68  ValueDisplayed: 10.0k  [0402]  (hidden comment: RC0402FR-0710KL)
R69  RC0603JR-0710RL  [FP-RC0603JR-0710RL_0603-MFG]  (value not drawn)
R70  ValueDisplayed: 10.0k  [0402]  (hidden comment: RC0402FR-0710KL)
R71  ValueDisplayed: 365  [0603]  (hidden comment: RT0603BRD07365RL)
R72  ValueDisplayed: 464  [0603]  (hidden comment: RT0603BRD07464RL)
RM1  ValueDisplayed: 0  [0402]  (hidden comment: CRCW04020000Z0ED)
RM2  ValueDisplayed: 0  [0402]  (hidden comment: CRCW04020000Z0ED)
RM3  ValueDisplayed: 0  [0402]  (hidden comment: CRCW04020000Z0ED)
RZ12  ValueDisplayed: 0  [0402]  (hidden comment: CRCW04020000Z0ED)
RZ13  ValueDisplayed: 0  [0402]  (hidden comment: CRCW04020000Z0ED)
RZ14  ValueDisplayed: 0  [0402]  (hidden comment: CRCW04020000Z0ED)
RZ15  ValueDisplayed: 0  [0402]  (hidden comment: CRCW04020000Z0ED)
RZ16  ValueDisplayed: 0  [0402]  (hidden comment: CRCW04020000Z0ED)
RZ17  ValueDisplayed: 0  [0402]  (hidden comment: CRCW04020000Z0ED)
RZ18  ValueDisplayed: 0  [0402]  (hidden comment: CRCW04020000Z0ED)
RZ19  ValueDisplayed: 0  [0402]  (hidden comment: CRCW04020000Z0ED)
RZ20  ValueDisplayed: 0  [0402]  (hidden comment: CRCW04020000Z0ED)
RZ21  ValueDisplayed: 0  [0402]  (hidden comment: CRCW04020000Z0ED)
RZ22  ValueDisplayed: 0  [0402]  (hidden comment: CRCW04020000Z0ED)
RZ23  ValueDisplayed: 0  [0402]  (hidden comment: CRCW04020000Z0ED)
RZ24  ValueDisplayed: 0  [0402]  (hidden comment: CRCW04020000Z0ED)
RZ25  ValueDisplayed: 0  [0402]  (hidden comment: CRCW04020000Z0ED)
RZ26  ValueDisplayed: 0  [0402]  (hidden comment: CRCW04020000Z0ED)
RZ27  ValueDisplayed: 0  [0402]  (hidden comment: CRCW04020000Z0ED)
RZ28  ValueDisplayed: 0  [0402]  (hidden comment: CRCW04020000Z0ED)
RZ29  ValueDisplayed: 0  [0402]  (hidden comment: CRCW04020000Z0ED)
RZ30  ValueDisplayed: 0  [0402]  (hidden comment: CRCW04020000Z0ED)
RZ31  ValueDisplayed: 0  [0402]  (hidden comment: CRCW04020000Z0ED)
RZ32  ValueDisplayed: 0  [0402]  (hidden comment: CRCW04020000Z0ED)
U2  TPS259850RQP  [RQP0026A-MFG]
U3  TPS259850RQP  [RQP0026A-MFG]
U4  TPS259850RQP  [RQP0026A-MFG]

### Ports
VIN, VOUT

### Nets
DVDT_1: RZ14.1 U2.4(DVDT)
DVDT_2: RZ21.1 U3.4(DVDT)
DVDT_3: RZ28.1 U4.4(DVDT)
EN: RZ12.2 RZ19.2 RZ26.2 ; off-sheet EN
EN_1: R55.2 RZ12.1 U2.18(EN/UVLO)
EN_2: R63.2 RZ19.1 U3.18(EN/UVLO)
EN_3: R68.2 RZ26.1 U4.18(EN/UVLO)
IMON: RZ18.2 RZ25.2 RZ32.2 ; off-sheet IMON
IMON_1: RZ18.1 U2.7(IMON)
IMON_2: RZ25.1 U3.7(IMON)
IMON_3: RZ32.1 U4.7(IMON)
IREF: U2.9(IREF) U3.9(IREF) U4.9(IREF) ; off-sheet IREF
PG: RZ17.2 RZ24.2 RZ31.2 ; off-sheet PG
PG_1: RZ17.1 U2.19(PG)
PG_2: RZ24.1 U3.19(PG)
PG_3: RZ31.1 U4.19(PG)
PGND: C49.2 C50.2 C51.2 C53.2 C54.2 C55.2 C57.2 C58.2 C59.2 RZ13.2 RZ20.2 RZ27.2
QGND: C52.1 C56.1 C60.1 R55.1 R60.1 R61.1 R62.1 R63.1 R65.1 R66.1 R67.1 R68.1 R70.1 R71.1 R72.1 RM1.2 RM2.2 RM3.2 RZ13.1 RZ20.1 RZ27.1 U2.14(GND) U3.14(GND) U4.14(GND)
SWEN: RZ16.2 RZ23.2 RZ30.2 ; off-sheet SWEN
SWEN_1: R60.2 RZ16.1 U2.21(SWEN)
SWEN_2: R65.2 RZ23.1 U3.21(SWEN)
SWEN_3: R70.2 RZ30.1 U4.21(SWEN)
TEMP: RZ15.2 RZ22.2 RZ29.2 ; off-sheet TEMP
TEMP_1: RZ15.1 U2.5(TEMP)
TEMP_2: RZ22.1 U3.5(TEMP)
TEMP_3: RZ29.1 U4.5(TEMP)
VIN: C49.1 C50.1 C53.1 C54.1 C57.1 C58.1 R59.2 R64.2 R69.2 U2.23(IN) U2.24(IN) U2.25(IN) U2.26(IN) U3.23(IN) U3.24(IN) U3.25(IN) U3.26(IN) U4.23(IN) U4.24(IN) U4.25(IN) U4.26(IN) ; port VIN
VOUT: C51.1 C55.1 C59.1 U2.10(OUT) U2.11(OUT) U2.12(OUT) U2.13(OUT) U3.10(OUT) U3.11(OUT) U3.12(OUT) U3.13(OUT) U4.10(OUT) U4.11(OUT) U4.12(OUT) U4.13(OUT) ; off-sheet VOUT, port VOUT
DVDT: RZ14.2 RZ21.2 RZ28.2 ; off-sheet DVDT
FLTb_1: U2.20(~{FLT}) ; off-sheet FLTb_1
FLTb_2: U3.20(~{FLT}) ; off-sheet FLTb_2
FLTb_3: U4.20(~{FLT}) ; off-sheet FLTb_3
ILIM_1: J6.2 J6.4 U2.8(ILIM) ; off-sheet ILIM_1
ILIM_2: J7.2 J7.4 U3.8(ILIM) ; off-sheet ILIM_2
ILIM_3: J8.2 J8.4 U4.8(ILIM) ; off-sheet ILIM_3
MODE_1: RM1.1 U2.17(MODE)
MODE_2: RM2.1 U3.17(MODE)
MODE_3: RM3.1 U4.17(MODE)
VDD_1: C52.2 R59.1 U2.22(VDD)
VDD_2: C56.2 R64.1 U3.22(VDD)
VDD_3: C60.2 R69.1 U4.22(VDD)
NetJ6_1: J6.1 R61.2
NetJ6_3: J6.3 R62.2
NetJ7_1: J7.1 R66.2
NetJ7_3: J7.3 R67.2
NetJ8_1: J8.1 R71.2
NetJ8_3: J8.3 R72.2

Not connected (* = marked no-connect by the designer): U2 1(CMPOUT) 2(CMPM) 3(CMPP) 6(ITIMER) 15(NC) 16(NC); U3 1(CMPOUT) 2(CMPM) 3(CMPP) 6(ITIMER) 15(NC) 16(NC); U4 1(CMPOUT) 2(CMPM) 3(CMPP) 6(ITIMER) 15(NC) 16(NC)

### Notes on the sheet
- (near R61) ILIM: [GILIM-> 1/55000], [VREF -> 1 V]
  365 -> 35 A Start-up Current Limit, 55 A Active Current Sharing Threshold,
  464 -> 28 A Start-up Current Limit, 44 A Active Current Sharing Threshold,
- (near R66) ILIM: [GILIM-> 1/55000], [VREF -> 1 V]
  365 -> 35 A Start-up Current Limit, 55 A Active Current Sharing Threshold,
  464 -> 28 A Start-up Current Limit, 44 A Active Current Sharing Threshold,
- (near R71) ILIM: [GILIM-> 1/55000], [VREF -> 1 V]
  365 -> 35 A Start-up Current Limit, 55 A Active Current Sharing Threshold,
  464 -> 28 A Start-up Current Limit, 44 A Active Current Sharing Threshold,

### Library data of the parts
C49 C53 C57 = CMP-0007052-1: as C19 on sheet TIDA-050077_DUT_1
C50 C54 C58 = CMP-0079602-1: as C20 on sheet TIDA-050077_DUT_1
C51 C55 C59 = CMP-0007356-5: as C24 on sheet TIDA-050077_DUT_1
C52 C56 C60 = CMP-0075366-1: CAP, CERM, 2.2 µF, 25 V,+/- 10%, X7S, 0603; Manufacturer: MuRata; TaMin_C: -55°C; Polarized: N; SizeAreaWB_mm2: 4.68; U/M: EA; Value: 2.2uF; TaMax_C: 125°C; SizeZ_mm: 1.0; SizeX_mm: 1.6; SizeY_mm: 0.8; Value2: 25V; SizeArea_mm2: 1.28; AEC Category: Q200
J6-J8 = CMP-0095565-1: as J3 on sheet TIDA-050077_DUT_1
R55 R60 R63 R65 R68 R70 = CMP-0078669-1: as R43 on sheet TIDA-050077_DUT_1
R59 R64 R69 = CMP-0095691-1: as R41 on sheet TIDA-050077_DUT_1
R61 R66 R71 = CMP-0024153-1: as RL1 on sheet TIDA-050077_DUT_1
R62 R67 R72 = CMP-0024259-2: as RL2 on sheet TIDA-050077_DUT_1
RM1-RM3 = CMP-0026822-2: RES, 0, 5%, 0.063 W, 0402; Manufacturer: Vishay-Dale; Power_W: 63mW; TempCo: 200 ppm/C; Value_Code: 0000; U/M: EA; Value: 0; EIA_Code: E24; SizeX_mm: 1; SizeY_mm: 0.5; SizeZ_mm: 0.6; Value2: 0.063W; VDC_V: 50V; AEC Category: Q200
RZ12-RZ32 = CMP-0026822-3: as RZ5 on sheet TIDA-050077_DUT_1
U2-U4 = CMP-0091052-1: as U1 on sheet TIDA-050077_DUT_1

## Sheet TIDA-050077_DUT_5_6.SchDoc
size 431 x 279 mm; Date: Not shown in title block; ApprovedBy: Not shown in title block; CheckedBy: Not shown in title block; Author: Not shown in title block; CompanyName: Not shown in title block; Engineer: Not shown in title block; Organization: Not shown in title block; Address1: Not shown in title block; Address2: Not shown in title block; Address3: Not shown in title block; Address4: Not shown in title block; DocumentNumber: 2; Revision: Use project parameter SCH_Rev; SheetNumber: 3; SheetTotal: 5; PageSetup: Record=PageOptions¦CenterHorizontal=True¦CenterVertical=True¦PrintScale=1.00¦XCorrection=1.00¦YCorrection=1.00¦PrintKind=0¦BorderSize=5000000¦LeftOffset=0¦BottomOffset=0¦Orientation=2¦PaperLength=1000¦PaperWidth=1000¦Scale=100¦PaperSource=15¦PrintQuality=600¦MediaType=1¦DitherType=10¦PaperKind=Letter¦PrintScaleMode=1
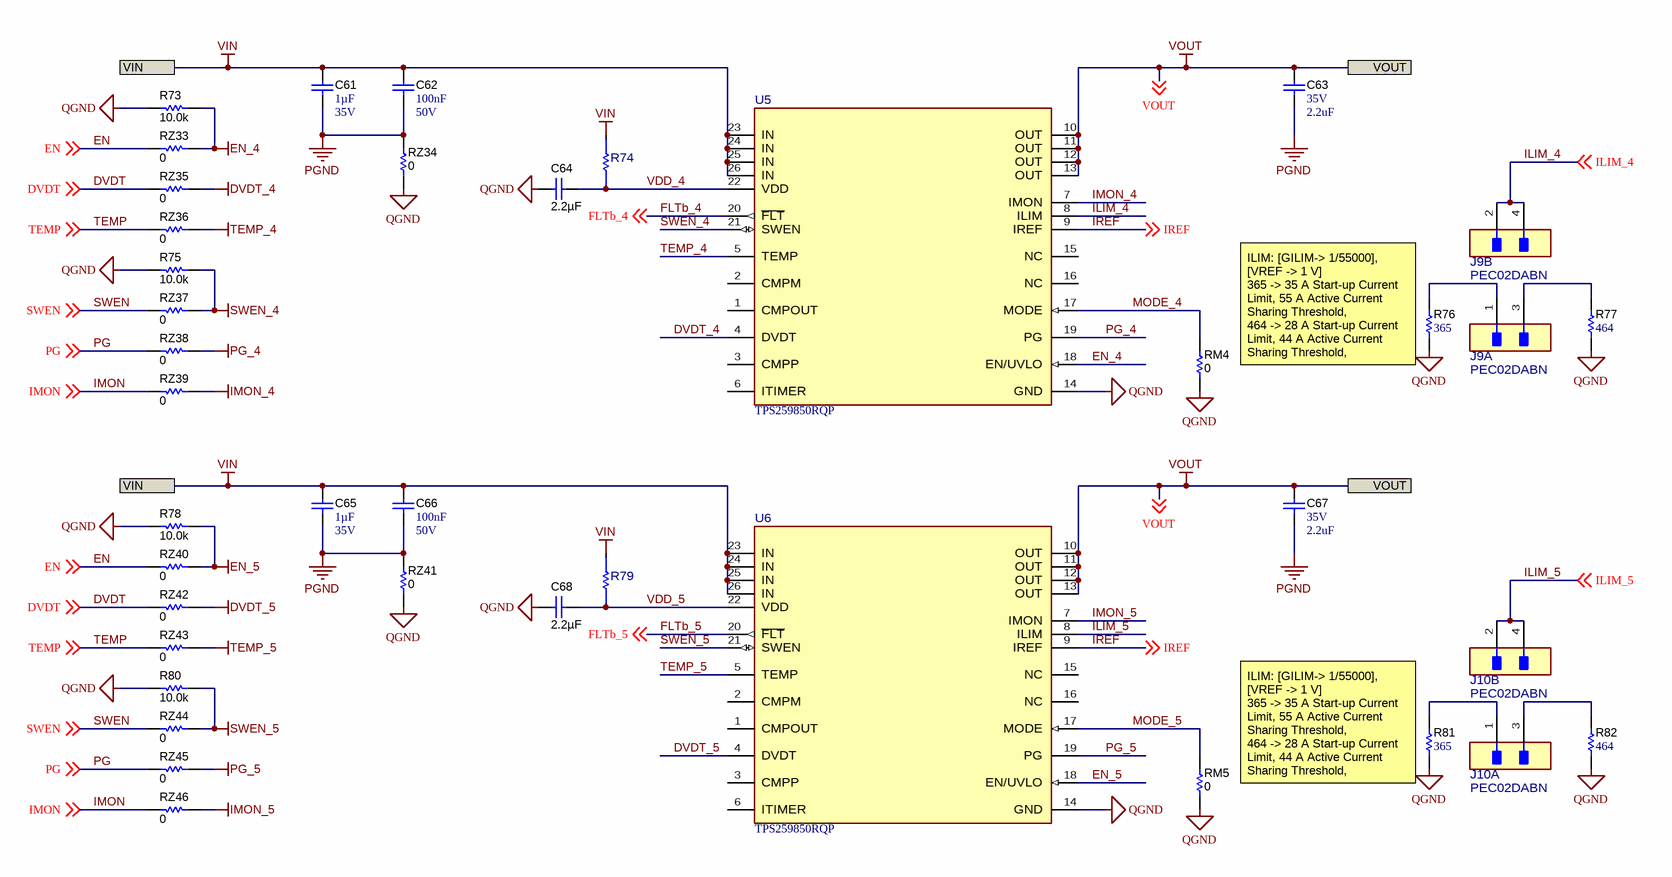
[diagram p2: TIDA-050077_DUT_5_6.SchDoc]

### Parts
C61  Cap_F: 1µF  VDC_V: 35V  [0603]  (hidden comment: C1608X7R1V105K080AC)
C62  Cap_F: 100nF  VDC_V: 50V  [0603]  (hidden comment: C0603C104K5RACAUTO)
C63  VDC_V: 35V  ValueDisplayed: 2.2uF  [0603]  (hidden comment: GRM188R6YA225KA12D)
C64  ValueDisplayed: 2.2µF  [0603]  (hidden comment: GRM188C71E225KE11D)
C65  Cap_F: 1µF  VDC_V: 35V  [0603]  (hidden comment: C1608X7R1V105K080AC)
C66  Cap_F: 100nF  VDC_V: 50V  [0603]  (hidden comment: C0603C104K5RACAUTO)
C67  VDC_V: 35V  ValueDisplayed: 2.2uF  [0603]  (hidden comment: GRM188R6YA225KA12D)
C68  ValueDisplayed: 2.2µF  [0603]  (hidden comment: GRM188C71E225KE11D)
J9  PEC02DABN  [FP-PEC02DABN_HDR4-MFG]  (parts A,B of 2)
J10  PEC02DABN  [FP-PEC02DABN_HDR4-MFG]  (parts A,B of 2)
R73  ValueDisplayed: 10.0k  [0402]  (hidden comment: RC0402FR-0710KL)
R74  RC0603JR-0710RL  [FP-RC0603JR-0710RL_0603-MFG]  (value not drawn)
R75  ValueDisplayed: 10.0k  [0402]  (hidden comment: RC0402FR-0710KL)
R76  ValueDisplayed: 365  [0603]  (hidden comment: RT0603BRD07365RL)
R77  ValueDisplayed: 464  [0603]  (hidden comment: RT0603BRD07464RL)
R78  ValueDisplayed: 10.0k  [0402]  (hidden comment: RC0402FR-0710KL)
R79  RC0603JR-0710RL  [FP-RC0603JR-0710RL_0603-MFG]  (value not drawn)
R80  ValueDisplayed: 10.0k  [0402]  (hidden comment: RC0402FR-0710KL)
R81  ValueDisplayed: 365  [0603]  (hidden comment: RT0603BRD07365RL)
R82  ValueDisplayed: 464  [0603]  (hidden comment: RT0603BRD07464RL)
RM4  ValueDisplayed: 0  [0402]  (hidden comment: CRCW04020000Z0ED)
RM5  ValueDisplayed: 0  [0402]  (hidden comment: CRCW04020000Z0ED)
RZ33  ValueDisplayed: 0  [0402]  (hidden comment: CRCW04020000Z0ED)
RZ34  ValueDisplayed: 0  [0402]  (hidden comment: CRCW04020000Z0ED)
RZ35  ValueDisplayed: 0  [0402]  (hidden comment: CRCW04020000Z0ED)
RZ36  ValueDisplayed: 0  [0402]  (hidden comment: CRCW04020000Z0ED)
RZ37  ValueDisplayed: 0  [0402]  (hidden comment: CRCW04020000Z0ED)
RZ38  ValueDisplayed: 0  [0402]  (hidden comment: CRCW04020000Z0ED)
RZ39  ValueDisplayed: 0  [0402]  (hidden comment: CRCW04020000Z0ED)
RZ40  ValueDisplayed: 0  [0402]  (hidden comment: CRCW04020000Z0ED)
RZ41  ValueDisplayed: 0  [0402]  (hidden comment: CRCW04020000Z0ED)
RZ42  ValueDisplayed: 0  [0402]  (hidden comment: CRCW04020000Z0ED)
RZ43  ValueDisplayed: 0  [0402]  (hidden comment: CRCW04020000Z0ED)
RZ44  ValueDisplayed: 0  [0402]  (hidden comment: CRCW04020000Z0ED)
RZ45  ValueDisplayed: 0  [0402]  (hidden comment: CRCW04020000Z0ED)
RZ46  ValueDisplayed: 0  [0402]  (hidden comment: CRCW04020000Z0ED)
U5  TPS259850RQP  [RQP0026A-MFG]
U6  TPS259850RQP  [RQP0026A-MFG]

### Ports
VIN, VOUT

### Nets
DVDT_4: RZ35.1 U5.4(DVDT)
DVDT_5: RZ42.1 U6.4(DVDT)
EN: RZ33.2 RZ40.2 ; off-sheet EN
EN_4: R73.2 RZ33.1 U5.18(EN/UVLO)
EN_5: R78.2 RZ40.1 U6.18(EN/UVLO)
IMON: RZ39.2 RZ46.2 ; off-sheet IMON
IMON_4: RZ39.1 U5.7(IMON)
IMON_5: RZ46.1 U6.7(IMON)
IREF: U5.9(IREF) U6.9(IREF) ; off-sheet IREF
PG: RZ38.2 RZ45.2 ; off-sheet PG
PG_4: RZ38.1 U5.19(PG)
PG_5: RZ45.1 U6.19(PG)
PGND: C61.2 C62.2 C63.2 C65.2 C66.2 C67.2 RZ34.2 RZ41.2
QGND: C64.1 C68.1 R73.1 R75.1 R76.1 R77.1 R78.1 R80.1 R81.1 R82.1 RM4.2 RM5.2 RZ34.1 RZ41.1 U5.14(GND) U6.14(GND)
SWEN: RZ37.2 RZ44.2 ; off-sheet SWEN
SWEN_4: R75.2 RZ37.1 U5.21(SWEN)
SWEN_5: R80.2 RZ44.1 U6.21(SWEN)
TEMP: RZ36.2 RZ43.2 ; off-sheet TEMP
TEMP_4: RZ36.1 U5.5(TEMP)
TEMP_5: RZ43.1 U6.5(TEMP)
VIN: C61.1 C62.1 C65.1 C66.1 R74.2 R79.2 U5.23(IN) U5.24(IN) U5.25(IN) U5.26(IN) U6.23(IN) U6.24(IN) U6.25(IN) U6.26(IN) ; port VIN
VOUT: C63.1 C67.1 U5.10(OUT) U5.11(OUT) U5.12(OUT) U5.13(OUT) U6.10(OUT) U6.11(OUT) U6.12(OUT) U6.13(OUT) ; off-sheet VOUT, port VOUT
DVDT: RZ35.2 RZ42.2 ; off-sheet DVDT
FLTb_4: U5.20(~{FLT}) ; off-sheet FLTb_4
FLTb_5: U6.20(~{FLT}) ; off-sheet FLTb_5
ILIM_4: J9.2 J9.4 U5.8(ILIM) ; off-sheet ILIM_4
ILIM_5: J10.2 J10.4 U6.8(ILIM) ; off-sheet ILIM_5
MODE_4: RM4.1 U5.17(MODE)
MODE_5: RM5.1 U6.17(MODE)
VDD_4: C64.2 R74.1 U5.22(VDD)
VDD_5: C68.2 R79.1 U6.22(VDD)
NetJ9_1: J9.1 R76.2
NetJ9_3: J9.3 R77.2
NetJ10_1: J10.1 R81.2
NetJ10_3: J10.3 R82.2

Not connected (* = marked no-connect by the designer): U5 1(CMPOUT) 2(CMPM) 3(CMPP) 6(ITIMER) 15(NC) 16(NC); U6 1(CMPOUT) 2(CMPM) 3(CMPP) 6(ITIMER) 15(NC) 16(NC)

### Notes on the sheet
- (near R76) ILIM: [GILIM-> 1/55000], [VREF -> 1 V]
  365 -> 35 A Start-up Current Limit, 55 A Active Current Sharing Threshold,
  464 -> 28 A Start-up Current Limit, 44 A Active Current Sharing Threshold,
- (near R81) ILIM: [GILIM-> 1/55000], [VREF -> 1 V]
  365 -> 35 A Start-up Current Limit, 55 A Active Current Sharing Threshold,
  464 -> 28 A Start-up Current Limit, 44 A Active Current Sharing Threshold,

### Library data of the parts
C61 C65 = CMP-0007052-1: as C19 on sheet TIDA-050077_DUT_1
C62 C66 = CMP-0079602-1: as C20 on sheet TIDA-050077_DUT_1
C63 C67 = CMP-0007356-5: as C24 on sheet TIDA-050077_DUT_1
C64 C68 = CMP-0075366-1: as C52 on sheet TIDA-050077_DUT_2_3_4
J9 J10 = CMP-0095565-1: as J3 on sheet TIDA-050077_DUT_1
R73 R75 R78 R80 = CMP-0078669-1: as R43 on sheet TIDA-050077_DUT_1
R74 R79 = CMP-0095691-1: as R41 on sheet TIDA-050077_DUT_1
R76 R81 = CMP-0024153-1: as RL1 on sheet TIDA-050077_DUT_1
R77 R82 = CMP-0024259-2: as RL2 on sheet TIDA-050077_DUT_1
RM4 RM5 = CMP-0026822-2: as RM1 on sheet TIDA-050077_DUT_2_3_4
RZ33-RZ46 = CMP-0026822-3: as RZ5 on sheet TIDA-050077_DUT_1
U5 U6 = CMP-0091052-1: as U1 on sheet TIDA-050077_DUT_1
